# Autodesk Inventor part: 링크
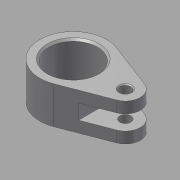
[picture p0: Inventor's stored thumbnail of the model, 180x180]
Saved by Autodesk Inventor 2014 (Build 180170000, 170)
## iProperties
Created: 2015-12
Part Number: 링크
Material: 강철, 연강
Document SubType Name: Modeling
Designer: mduedu
Density: 7.86 g/cm^3
Appearance: 강철
Author: mduedu
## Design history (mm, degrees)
sketch "스케치1"
  geometry: L1 (6.429, -16.813)-(30.857, -7.472); L2 (6.429, 16.813)-(30.857, 7.472); A1 r 18 centre (0, 0) between (6.429, 16.813) and (6.429, -16.813); A2 r 8 centre (28, 0) between (30.857, -7.472) and (30.857, 7.472); 1 further point
  constraints: 4 end point, 4 point on circle, 4 tangent, 2 centre point, 1 coincident, 1 horizontal alignment
  dimensions: "d0" = 18 radius of A1; "d1" = 8 radius of A2; "d2" = 28 distance of A2.centre point (0, 0)
extrude "돌출1" new body sketch "스케치1" stored distance "d3" = 20; taper "d4" = 0 deg
sketch "스케치2"
  geometry: L1 (6.429, 16.813)-(30.857, 7.472) reference; L2 (30.857, -7.472)-(6.429, -16.813) reference; L3 (16, 13.153)-(16, -13.153); A1 r 8 centre (28, 0) between (30.857, -7.472) and (30.857, 7.472) reference; 1 further point
  constraints: 2 end point, 2 point on line, 1 vertical
  dimensions: "d5" = 20 dimension on A1 L3
extrude "돌출2" cut sketch "스케치2" stored distance "d6" = 8; taper "d7" = 0 deg
hole "구멍1" diameter "d10" = 26; stored, may be unused: countersink angle "d14" = 90 deg, drill point angle "d16" = 118 deg; dims "d8" = 10, "d9" = 10, "d11" = 6, "d12" = 4, "d13" = 2, "d15" = 8
hole "구멍2" diameter "d19" = 6; stored, may be unused: countersink angle "d23" = 90 deg, drill point angle "d25" = 118 deg; dims "d20" = 6, "d21" = 4, "d22" = 2, "d24" = 8, "d32" = 10, "d33" = 10
chamfer "모따기1" distance "d26" = 1; stored, may be unused: second distance "d27" = 2, angle "d28" = 45 deg
chamfer "모따기2" distance "d29" = 0.5; stored, may be unused: second distance "d30" = 2, angle "d31" = 45 deg
node "솔리드1"
